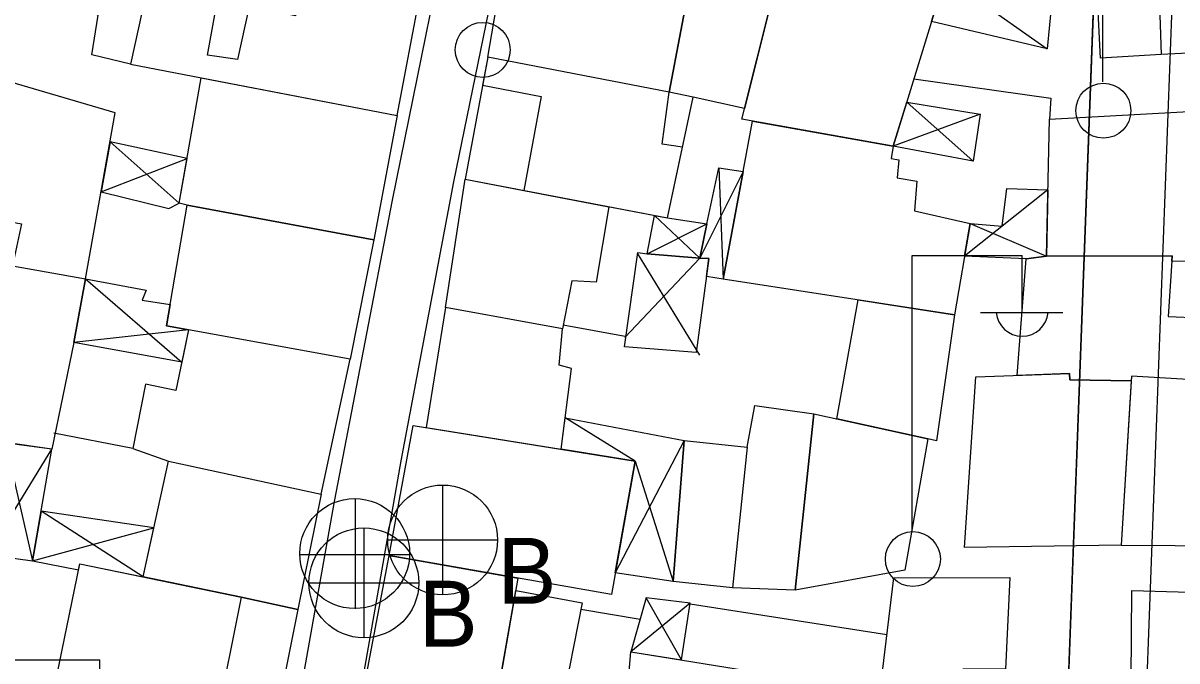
# Model space of a CAD drawing. Extents: x 417997 to 421451, y 4451742 to 4455216.
# Drawn here: x 419851.8 to 419925.3, y 4452543.9 to 4452584.5 of the extents above; entities that cross this region are included whole.
import ezdxf

# ---------------------------------------------------------------- set-up
doc = ezdxf.new("R2010")
doc.units = 0
for name, color, linetype in [('ADA', 7, 'Continuous'), ('B_Mesken', 7, 'Continuous'), ('B_Sundurma', 7, 'Continuous'), ('B_Teras', 7, 'Continuous'), ('KALDIRIM', 7, 'Continuous'), ('PL_TİCK', 7, 'Continuous'), ('S_Elektrik_Diregi', 7, 'Continuous'), ('S_Rogar_Kapagi', 7, 'Continuous'), ('S_Rogar_Kapagi_Buski', 7, 'Continuous'), ('Sinir_Duvar_tek_tarafa_ait', 7, 'Continuous'), ('TR_TİCK', 7, 'Continuous'), ('Yol_Sose', 7, 'Continuous')]:
    doc.layers.add(name, color=color, linetype=linetype)

msp = doc.modelspace()

# ---------------------------------------------------------------- linework, layer by layer
at = {"layer": 'ADA'}
msp.add_line((419923.418, 4452678.243), (419918.101, 4452535.298), dxfattribs=at)
msp.add_line((419923.418, 4452678.243), (419918.101, 4452535.298), dxfattribs=at)
at = {"layer": 'B_Mesken'}
for points in [[(419926.072, 4452593.728), (419927.986, 4452593.88), (419933.932, 4452594.229), (419935.15, 4452583.024), (419924.278, 4452582.484), (419920.414, 4452582.257), (419919.874, 4452593.238)], [(419858.616, 4452581.868), (419856.165, 4452582.46), (419856.567, 4452584.999), (419848.324, 4452587.398), (419849.282, 4452590.824), (419854.836, 4452589.49), (419860.07, 4452588.462)], [(419881.386, 4452582.321), (419882.711, 4452590.024), (419894.436, 4452587.918), (419892.948, 4452580.089)], [(419897.563, 4452578.369), (419900.501, 4452590.041), (419901.148, 4452590.069), (419910.536, 4452587.433), (419907.218, 4452576.652)], [(419869.475, 4452587.834), (419869.137, 4452584.944), (419866.184, 4452585.547), (419865.441, 4452582.165), (419863.524, 4452582.455), (419864.669, 4452588.769), (419860.305, 4452589.525), (419858.616, 4452581.868), (419875.619, 4452578.594), (419877.09, 4452586.353)], [(419894.436, 4452587.918), (419899.703, 4452586.868), (419897.735, 4452579.054), (419894.462, 4452579.777), (419892.948, 4452580.089)], [(419881.386, 4452582.321), (419879.953, 4452574.546), (419892.832, 4452572.081), (419894.462, 4452579.777), (419892.948, 4452580.089)], [(419848.064, 4452572.39), (419851.686, 4452571.701), (419851.113, 4452569.028), (419855.75, 4452568.19), (419857.658, 4452578.767), (419849.902, 4452581.049)], [(419862.229, 4452572.89), (419861.73, 4452573.02), (419863.124, 4452581), (419875.619, 4452578.594), (419874.122, 4452570.686)], [(419917.171, 4452578.376), (419929.157, 4452579.029), (419928.973, 4452569.291), (419924.97, 4452569.329), (419924.991, 4452569.657), (419916.982, 4452569.65)], [(419907.218, 4452576.652), (419907.084, 4452575.857), (419907.585, 4452575.778), (419907.471, 4452574.642), (419908.721, 4452574.43), (419908.573, 4452572.534), (419912.116, 4452571.728), (419911.119, 4452565.902), (419896.383, 4452568.183), (419898.257, 4452578.245)], [(419878.688, 4452566.375), (419879.953, 4452574.546), (419879.953, 4452574.546), (419883.686, 4452573.832), (419889.103, 4452572.795), (419888.292, 4452567.989), (419886.743, 4452568.064), (419886.155, 4452565.018)], [(419860.93, 4452565.212), (419862.229, 4452572.89), (419874.122, 4452570.686), (419872.611, 4452563.089)], [(419847.488, 4452569.234), (419847.49, 4452569.684), (419851.113, 4452569.028), (419855.75, 4452568.19), (419855.008, 4452564.152), (419853.612, 4452557.343), (419850.668, 4452557.777), (419845.94, 4452558.391)], [(419915.107, 4452562.052), (419915.684, 4452569.478), (419916.982, 4452569.65), (419924.991, 4452569.657), (419924.735, 4452565.793), (419928.764, 4452565.634), (419929.055, 4452563.504), (419928.556, 4452561.617), (419927.998, 4452561.533), (419926.372, 4452561.759), (419922.402, 4452562.008), (419922.383, 4452561.697), (419918.468, 4452561.76), (419918.446, 4452562.161)], [(419903.625, 4452559.284), (419904.975, 4452566.853), (419911.119, 4452565.902), (419909.981, 4452557.885), (419909.421, 4452558.01)], [(419886.061, 4452557.345), (419886.729, 4452562.487), (419885.938, 4452562.711), (419886.155, 4452565.018), (419878.688, 4452566.375), (419877.465, 4452558.733)], [(419862.323, 4452564.959), (419861.523, 4452561.087), (419859.571, 4452561.488), (419858.783, 4452557.384), (419861.042, 4452556.577), (419870.767, 4452554.486), (419872.611, 4452563.089)], [(419921.744, 4452551.242), (419911.765, 4452551.088), (419912.474, 4452561.966), (419918.446, 4452562.161), (419918.468, 4452561.76), (419922.383, 4452561.697)], [(419927.76, 4452559.228), (419926.098, 4452559.253), (419926.372, 4452561.759), (419922.402, 4452562.008), (419921.744, 4452551.242), (419928.621, 4452551.198), (419929, 4452559.19)], [(419896.97, 4452548.515), (419893.205, 4452548.925), (419893.894, 4452557.911), (419897.906, 4452557.485), (419898.404, 4452560.123), (419902.165, 4452559.604), (419900.976, 4452548.369)], [(419902.165, 4452559.604), (419909.421, 4452558.01), (419907.961, 4452549.639), (419900.976, 4452548.369)], [(419875.109, 4452550.582), (419876.625, 4452558.868), (419890.778, 4452556.583), (419889.268, 4452548.094)], [(419859.426, 4452549.22), (419861.042, 4452556.577), (419870.767, 4452554.486), (419869.281, 4452547.144), (419865.674, 4452547.933)], [(419873.655, 4452542.981), (419875.109, 4452550.582), (419883.306, 4452549.142), (419882.019, 4452541.836)], [(419865.674, 4452547.933), (419869.281, 4452547.144), (419867.699, 4452539.206), (419864.074, 4452539.986), (419859.799, 4452540.905), (419858.237, 4452541.122), (419853.754, 4452542.084), (419855.4, 4452550.049)], [(419906.901, 4452542.412), (419906.444, 4452542.485), (419907.258, 4452549.145), (419914.648, 4452549.167), (419914.375, 4452543.34), (419911.644, 4452543.333), (419911.568, 4452542.473), (419909.511, 4452542.621), (419910.034, 4452541.18), (419908.171, 4452540.78), (419906.901, 4452542.412)], [(419883.165, 4452548.343), (419887.391, 4452547.569), (419886.053, 4452540.769), (419881.938, 4452541.511), (419882.019, 4452541.836)], [(419926.104, 4452548.247), (419931.998, 4452548.215), (419932.057, 4452545.793), (419931.858, 4452537.728), (419927.963, 4452537.881), (419927.907, 4452539.933), (419922.347, 4452539.868), (419922.426, 4452548.344)], [(419890.149, 4452540.139), (419890.509, 4452544.44), (419899.854, 4452542.933), (419899.345, 4452538.78), (419897.24, 4452539.127)]]:
    msp.add_lwpolyline(points, close=True, dxfattribs=at)
at = {"layer": 'B_Sundurma'}
for p, q in [((419910.536, 4452587.433), (419917.03, 4452582.853)), ((419908.081, 4452579.455), (419912.31, 4452575.685)), ((419912.757, 4452578.681), (419907.218, 4452576.652)), ((419861.73, 4452573.02), (419857.325, 4452576.921)), ((419856.749, 4452573.731), (419862.229, 4452575.875)), ((419897.658, 4452575.029), (419894.899, 4452569.515)), ((419896.113, 4452575.27), (419896.383, 4452568.183)), ((419917.073, 4452573.869), (419911.76, 4452569.647)), ((419892.015, 4452572.237), (419894.899, 4452569.515)), ((419891.534, 4452569.784), (419895.353, 4452571.694)), ((419912.116, 4452571.728), (419916.982, 4452569.65)), ((419894.904, 4452563.344), (419890.923, 4452569.833)), ((419890.129, 4452564.457), (419894.899, 4452569.515)), ((419855.75, 4452568.19), (419861.895, 4452562.887)), ((419862.323, 4452564.959), (419855.008, 4452564.152)), ((419890.778, 4452556.583), (419886.322, 4452559.356)), ((419849.483, 4452550.65), (419853.612, 4452557.343)), ((419850.668, 4452557.777), (419852.388, 4452550.233)), ((419893.894, 4452557.911), (419889.512, 4452549.469)), ((419890.778, 4452556.583), (419893.205, 4452548.925)), ((419859.426, 4452549.22), (419852.934, 4452553.401)), ((419852.388, 4452550.233), (419860.112, 4452552.345)), ((419893.729, 4452543.921), (419891.48, 4452547.879)), ((419894.28, 4452547.533), (419890.509, 4452544.44))]:
    msp.add_line(p, q, dxfattribs=at)
for points in [[(419910.536, 4452587.433), (419911.414, 4452587.186), (419916.502, 4452586.152), (419917.316, 4452585.916), (419917.03, 4452582.853), (419909.661, 4452584.589)], [(419908.081, 4452579.455), (419912.757, 4452578.681), (419912.31, 4452575.685), (419907.218, 4452576.652)], [(419856.749, 4452573.731), (419861.072, 4452572.679), (419861.73, 4452573.02), (419862.229, 4452575.875), (419857.325, 4452576.921)], [(419895.353, 4452571.694), (419896.113, 4452575.27), (419897.658, 4452575.029), (419896.383, 4452568.183), (419895.317, 4452568.34), (419895.473, 4452569.489), (419894.899, 4452569.515)], [(419912.116, 4452571.728), (419914.158, 4452571.553), (419914.446, 4452573.949), (419917.073, 4452573.869), (419916.982, 4452569.65), (419915.684, 4452569.478), (419911.76, 4452569.647)], [(419891.534, 4452569.784), (419892.015, 4452572.237), (419892.832, 4452572.081), (419895.353, 4452571.694), (419894.899, 4452569.515)], [(419890.101, 4452563.877), (419890.955, 4452569.871), (419891.534, 4452569.784), (419894.899, 4452569.515), (419895.473, 4452569.489), (419894.665, 4452563.517)], [(419855.75, 4452568.19), (419859.616, 4452567.476), (419859.366, 4452566.839), (419861.157, 4452566.555), (419860.93, 4452565.212), (419862.323, 4452564.959), (419861.895, 4452562.887), (419855.008, 4452564.152)], [(419886.322, 4452559.356), (419893.894, 4452557.911), (419893.205, 4452548.925), (419889.512, 4452549.469), (419890.778, 4452556.583), (419886.061, 4452557.345)], [(419850.668, 4452557.777), (419849.483, 4452550.65), (419852.388, 4452550.233), (419853.612, 4452557.343), (419851.22, 4452557.662)], [(419852.388, 4452550.233), (419855.32, 4452549.665), (419855.4, 4452550.049), (419859.426, 4452549.22), (419860.112, 4452552.345), (419852.934, 4452553.401)], [(419893.729, 4452543.921), (419894.28, 4452547.533), (419891.48, 4452547.879), (419890.509, 4452544.44)]]:
    msp.add_lwpolyline(points, close=True, dxfattribs=at)
at = {"layer": 'B_Teras'}
for points in [[(419926.072, 4452593.728), (419926.192, 4452591.855), (419929.027, 4452591.978), (419929.248, 4452586.368), (419924.165, 4452586.289), (419924.278, 4452582.484), (419920.414, 4452582.257), (419919.874, 4452593.238)], [(419881.057, 4452580.538), (419884.791, 4452579.812), (419883.686, 4452573.832), (419892.832, 4452572.081), (419893.787, 4452576.592), (419892.505, 4452576.786), (419892.948, 4452580.089), (419881.386, 4452582.321)], [(419893.205, 4452548.925), (419893.894, 4452557.911), (419897.906, 4452557.485), (419896.97, 4452548.515)], [(419853.754, 4452542.084), (419855.4, 4452550.049), (419865.674, 4452547.933), (419864.074, 4452539.986), (419859.799, 4452540.905), (419858.237, 4452541.122)], [(419922.347, 4452539.868), (419922.426, 4452548.344), (419926.104, 4452548.247), (419926.163, 4452545.018), (419930.441, 4452545.06), (419930.432, 4452545.743), (419932.057, 4452545.793), (419931.858, 4452537.728), (419927.963, 4452537.881), (419927.907, 4452539.933)]]:
    msp.add_lwpolyline(points, close=True, dxfattribs=at)
at = {"layer": 'KALDIRIM'}
msp.add_line((419928.568, 4452682.181), (419923.098, 4452535.112), dxfattribs=at)
msp.add_line((419928.568, 4452682.181), (419923.098, 4452535.112), dxfattribs=at)
at = {"layer": 'PL_TİCK'}
msp.add_lwpolyline([(419843.661, 4452525.165), (419917.525, 4452519.802), (419918.101, 4452535.298), (419923.418, 4452678.243), (419918.769, 4452681.966), (419824.159, 4452657.046), (419820.24, 4452650.857), (419830.412, 4452596.267), (419834.475, 4452574.463), (419843.661, 4452525.165)], dxfattribs=at)
msp.add_lwpolyline([(419843.661, 4452525.165), (419917.525, 4452519.802), (419918.101, 4452535.298), (419923.418, 4452678.243), (419918.769, 4452681.966), (419824.159, 4452657.046), (419820.24, 4452650.857), (419830.412, 4452596.267), (419834.475, 4452574.463), (419843.661, 4452525.165)], dxfattribs=at)
at = {"layer": 'S_Elektrik_Diregi'}
for p, q in [((419920.572, 4452580.745), (419920.572, 4452598.245)), ((419908.433, 4452552.184), (419908.433, 4452569.685)), ((419908.433, 4452569.685), (419915.433, 4452569.685)), ((419915.433, 4452566.185), (419915.433, 4452569.685)), ((419912.773, 4452566.045), (419918.023, 4452566.045)), ((419849.665, 4452543.937), (419856.665, 4452543.937)), ((419856.665, 4452540.436), (419856.665, 4452543.937))]:
    msp.add_line(p, q, dxfattribs=at)
for centre in [(419881.065, 4452582.782), (419920.608, 4452578.91), (419908.469, 4452550.349)]:
    msp.add_circle(centre, 1.75, dxfattribs=at)
msp.add_arc((419915.434, 4452566.197), 1.658, 184.83843, 355.14641, dxfattribs=at)
at = {"layer": 'S_Rogar_Kapagi'}
for p, q in [((419872.961, 4452547.17), (419872.961, 4452554.17)), ((419869.391, 4452550.635), (419876.391, 4452550.635))]:
    msp.add_line(p, q, dxfattribs=at)
msp.add_circle((419872.908, 4452550.698), 3.5, dxfattribs=at)
at = {"layer": 'S_Rogar_Kapagi_Buski'}
for p, q in [((419878.512, 4452555.065), (419878.512, 4452548.065)), ((419873.492, 4452552.335), (419873.492, 4452545.335)), ((419875.012, 4452551.565), (419882.012, 4452551.565)), ((419869.992, 4452548.835), (419876.992, 4452548.835))]:
    msp.add_line(p, q, dxfattribs=at)
for centre in [(419878.512, 4452551.565), (419873.492, 4452548.835)]:
    msp.add_circle(centre, 3.5, dxfattribs=at)
at = {"layer": 'Sinir_Duvar_tek_tarafa_ait'}
for points in [[(419908.536, 4452580.934), (419917.263, 4452579.711), (419917.171, 4452578.376)], [(419890.138, 4452564.517), (419886.198, 4452565.242)], [(419858.783, 4452557.384), (419853.732, 4452558.37)], [(419887.309, 4452547.152), (419891.094, 4452546.512)], [(419894.273, 4452547.488), (419906.818, 4452545.55)]]:
    msp.add_lwpolyline(points, dxfattribs=at)
at = {"layer": 'TR_TİCK'}
msp.add_lwpolyline([(419918.101, 4452535.298), (419923.418, 4452678.243), (419918.769, 4452681.966), (419824.159, 4452657.046), (419820.24, 4452650.857), (419830.412, 4452596.267), (419834.475, 4452574.463), (419843.661, 4452525.165), (419917.525, 4452519.802), (419918.101, 4452535.298)], dxfattribs=at)
msp.add_lwpolyline([(419918.101, 4452535.298), (419923.418, 4452678.243), (419918.769, 4452681.966), (419824.159, 4452657.046), (419820.24, 4452650.857), (419830.412, 4452596.267), (419834.475, 4452574.463), (419843.661, 4452525.165), (419917.525, 4452519.802), (419918.101, 4452535.298)], dxfattribs=at)
at = {"layer": 'Yol_Sose'}
for points in [[(419879.818, 4452595.474), (419875.297, 4452573.214), (419871.595, 4452554.019), (419868.593, 4452537.051), (419866.15, 4452526.437), (419865.957, 4452526.188), (419865.422, 4452525.862), (419856.055, 4452527.056), (419843.618, 4452528.615), (419832.994, 4452528.79), (419832.429, 4452528.859), (419831.978, 4452529.081), (419831.597, 4452529.473), (419830.674, 4452536.765)], [(419836.66, 4452514.816), (419833.015, 4452523.388), (419832.963, 4452524.206), (419839.372, 4452524.879), (419848.172, 4452525.762), (419855.641, 4452524.166), (419865.536, 4452522.199), (419868.806, 4452521.852), (419869.259, 4452521.878), (419869.684, 4452522.125), (419872.64, 4452538.201), (419875.867, 4452556.6), (419879.216, 4452574.38), (419883.34, 4452594.49)]]:
    msp.add_lwpolyline(points, dxfattribs=at)

# ---------------------------------------------------------------- texts
at = {"layer": 'S_Rogar_Kapagi_Buski'}
for p in [(419882.012, 4452547.501), (419876.992, 4452544.771)]:
    msp.add_text('B', height=4.2, dxfattribs=at).set_placement(p)

doc.saveas('drawing.dxf')
